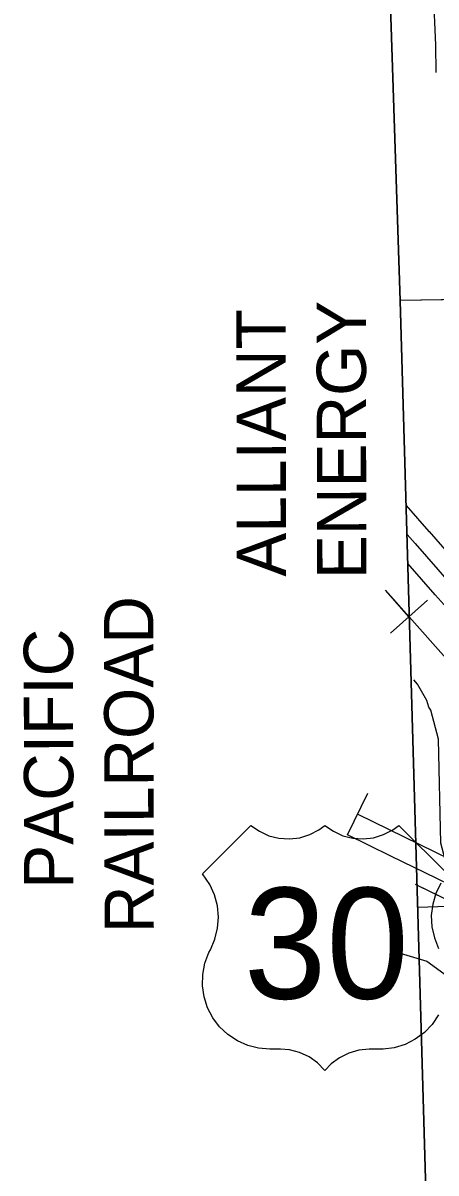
# Model space of a CAD drawing. Extents: x 128.7 to 185.5, y -21.4 to 12.6.
# Drawn here: x 133.449 to 134.119, y -9.118 to -7.251 of the extents above; entities that cross this region are included whole.
import ezdxf

# ---------------------------------------------------------------- set-up
doc = ezdxf.new("R2010")
doc.units = 0
for name, color, linetype in [('tdCoClipBndry', 7, 'Continuous'), ('tdCoCoBndry', 7, 'Continuous'), ('tdCoHydroRiver', 7, 'Continuous'), ('tdCoPipe', 7, 'Continuous'), ('tdCoPipeTxt', 7, 'Continuous'), ('tdCoPriCL', 7, 'Continuous'), ('tdCoPrimary', 7, 'Continuous'), ('tdCoPriNonDiv', 7, 'Continuous'), ('tdCoPriNonDivCL', 7, 'Continuous'), ('tdCoRRCL', 7, 'Continuous'), ('tdCoRROwnerTxt', 7, 'Continuous'), ('tdCoSecRteBand', 7, 'Continuous'), ('tdCoSecRteCL', 7, 'Continuous'), ('tdCoSectLine', 7, 'Continuous'), ('tdCoSectLinePart', 7, 'Continuous'), ('tdCoShieldUsRte', 7, 'Continuous'), ('tdCoSurfAsphalt', 7, 'Continuous')]:
    doc.layers.add(name, color=color, linetype=linetype)

msp = doc.modelspace()

# ---------------------------------------------------------------- linework, layer by layer
at = {"layer": 'tdCoClipBndry'}
msp.add_lwpolyline([(140.0473, -13.6827), (139.3409, -13.68), (138.3408, -13.7014), (135.3417, -13.7884), (134.3324, -13.8229), (134.2979, -13.818), (134.2605, -13.7958), (134.2397, -13.7678), (134.2291, -13.7257), (134.1751, -11.7221), (134.1418, -10.7117), (134.1187, -9.7087), (134.0612, -7.7025), (133.8962, -2.6807)], dxfattribs=at)
at = {"layer": 'tdCoCoBndry'}
msp.add_lwpolyline([(133.8962, -2.6807), (134.0612, -7.7025), (134.1187, -9.7087), (134.1418, -10.7117), (134.1751, -11.7221), (134.2291, -13.7257), (134.2397, -13.7678), (134.2605, -13.7958), (134.2979, -13.818), (134.3318, -13.8228), (134.3294, -13.723), (134.3001, -12.7212), (134.2754, -11.7191), (134.2421, -10.7094), (134.219, -9.7062), (134.1879, -8.683), (134.1615, -7.6994), (134.1297, -6.7029)], dxfattribs=at)
at = {"layer": 'tdCoHydroRiver'}
for points in [[(134.1586, -8.8038), (134.1525, -8.6509), (134.1454, -8.6259), (134.1339, -8.6088), (134.1268, -8.5822), (134.1234, -8.4135), (134.1109, -8.3665), (134.1076, -8.3619), (134.1041, -8.3509), (134.0892, -8.3245), (134.0831, -8.3171)], [(134.0553, -8.7596), (134.1041, -8.7738), (134.1379, -8.7981), (134.1586, -8.8038), (134.1604, -8.8116), (134.2009, -8.8451), (134.2621, -8.8891), (134.3164, -8.9096), (134.4386, -8.9312), (134.4721, -8.9444), (134.5193, -8.9919), (134.5452, -9.0148), (134.5835, -9.0294), (134.9473, -9.0565), (135.0122, -9.0656), (135.0921, -9.098), (135.126, -9.1238)]]:
    msp.add_lwpolyline(points, dxfattribs=at)
at = {"layer": 'tdCoPipe'}
msp.add_line((134.045, -8.2417), (134.1053, -8.1882), dxfattribs=at)
for points in [[(136.9009, -9.4255), (136.8169, -9.4094), (136.5505, -9.3406), (136.5159, -9.3231), (136.4089, -9.2225), (136.4044, -9.218), (135.9635, -8.7378), (135.3912, -8.758), (135.204, -8.7612), (134.6962, -8.7684), (134.6297, -8.7639), (134.5618, -8.7314), (134.4564, -8.6441), (134.037, -8.172)], [(134.0751, -8.215), (134.037, -8.172)]]:
    msp.add_lwpolyline(points, dxfattribs=at)
at = {"layer": 'tdCoPriCL'}
msp.add_lwpolyline([(134.0884, -8.6507), (134.1751, -8.6926)], dxfattribs=at)
at = {"layer": 'tdCoPrimary'}
for points in [[(134.0884, -8.6505), (134.1754, -8.6926), (134.1883, -8.6989)], [(134.0884, -8.6505), (134.1754, -8.6926), (134.1883, -8.6989)], [(134.0884, -8.6505), (134.1754, -8.6926)]]:
    msp.add_lwpolyline(points, dxfattribs=at)
at = {"layer": 'tdCoPriNonDiv'}
msp.add_lwpolyline([(134.0851, -8.6491), (134.3608, -8.7836), (134.4273, -8.8152), (134.4917, -8.8423), (134.5629, -8.8687), (134.6384, -8.8922), (135.3035, -9.0723), (136.2808, -9.3366)], dxfattribs=at)
at = {"layer": 'tdCoPriNonDivCL'}
for points in [[(134.0884, -8.6507), (134.1751, -8.6926)], [(134.0884, -8.6507), (134.1751, -8.6926), (134.1879, -8.6989)]]:
    msp.add_lwpolyline(points, dxfattribs=at)
at = {"layer": 'tdCoRRCL'}
msp.add_line((133.9757, -8.5688), (134.0086, -8.5014), dxfattribs=at)
for points in [[(133.992, -8.5352), (134.2166, -8.645), (134.4406, -8.754), (134.4603, -8.7626), (134.4791, -8.7707), (134.4969, -8.7778), (134.5147, -8.7849), (134.5414, -8.7951), (134.5789, -8.8085), (134.6146, -8.82), (134.6502, -8.8316), (134.6697, -8.8374), (134.911, -8.9025), (135.152, -8.9678), (135.3934, -9.0327), (135.6349, -9.098)], [(135.481, -9.095), (135.3832, -9.0688), (135.2626, -9.0366), (135.1848, -9.0154), (135.0629, -8.9826), (134.9732, -8.9582), (134.8705, -8.9307), (134.774, -8.9047), (134.7045, -8.8861), (134.6398, -8.868), (134.5685, -8.845), (134.531, -8.8316), (134.5042, -8.8214), (134.4686, -8.8072), (134.4311, -8.791), (134.3826, -8.7687), (134.3257, -8.7406), (134.2712, -8.7136), (134.1872, -8.6725), (134.1205, -8.64), (134.0458, -8.6033), (133.9755, -8.5689)]]:
    msp.add_lwpolyline(points, dxfattribs=at)
at = {"layer": 'tdCoSecRteBand'}
for points in [[(134.1193, -7.3318), (134.1186, -7.2875), (134.1152, -7.2001)], [(134.0707, -8.0346), (134.1077, -8.0764), (134.1078, -8.0765), (134.1078, -8.0766), (134.1443, -8.1185)], [(134.1371, -8.2012), (134.1178, -8.1794), (134.1177, -8.1793), (134.1176, -8.1792), (134.0734, -8.1285)]]:
    msp.add_lwpolyline(points, dxfattribs=at)
at = {"layer": 'tdCoSecRteCL'}
msp.add_lwpolyline([(134.0721, -8.0815), (134.0852, -8.0963), (134.1402, -8.1594), (134.1617, -8.1836), (134.1689, -8.1919), (134.1749, -8.1988), (134.1889, -8.2147), (134.241, -8.2733), (134.2735, -8.3113), (134.3746, -8.4265), (134.4513, -8.5148), (134.5103, -8.5816), (134.5372, -8.6124), (134.5561, -8.6341), (134.5687, -8.6437), (134.5801, -8.6531), (134.5921, -8.6593), (134.6136, -8.6701), (134.6286, -8.6763), (134.6457, -8.6802), (134.6703, -8.6835), (134.6968, -8.6838)], dxfattribs=at)
at = {"layer": 'tdCoSectLine'}
for points in [[(134.0612, -7.7013), (134.1612, -7.6994)], [(134.0894, -8.6862), (134.1875, -8.683)]]:
    msp.add_lwpolyline(points, dxfattribs=at)
at = {"layer": 'tdCoSectLinePart'}
for points in [[(134.0612, -7.7013), (134.1307, -7.7)], [(134.0894, -8.6862), (134.1875, -8.683)]]:
    msp.add_lwpolyline(points, dxfattribs=at)
at = {"layer": 'tdCoShieldUsRte'}
for points in [[(134.1233, -8.8613), (134.1129, -8.8765), (134.1002, -8.8897), (134.0854, -8.9007), (134.069, -8.909), (134.0514, -8.9144), (134.0331, -8.9169), (134.024, -8.917), (134.0107, -8.917), (133.9938, -8.9185), (133.9776, -8.9231), (133.9624, -8.9306), (133.9488, -8.9406), (133.9387, -8.9513), (133.9269, -8.9392), (133.9131, -8.9294), (133.8978, -8.9223), (133.8814, -8.9181), (133.8668, -8.917), (133.8497, -8.917), (133.8313, -8.9154), (133.8135, -8.9109), (133.7967, -8.9034), (133.7814, -8.8932), (133.768, -8.8805), (133.7569, -8.8659), (133.7484, -8.8495), (133.7428, -8.832), (133.7401, -8.8138), (133.7406, -8.7954), (133.7441, -8.7774), (133.7506, -8.7601), (133.753, -8.7554), (133.7603, -8.7385), (133.7647, -8.7206), (133.766, -8.7023), (133.7643, -8.684), (133.7595, -8.6662), (133.7518, -8.6495), (133.7399, -8.6324), (133.8187, -8.5535), (133.8325, -8.5632), (133.8479, -8.5703), (133.8643, -8.5745), (133.8811, -8.5756), (133.8979, -8.5736), (133.9141, -8.5686), (133.929, -8.5607), (133.9387, -8.5535), (133.9525, -8.5632), (133.9679, -8.5703), (133.9843, -8.5745), (134.0011, -8.5756), (134.0179, -8.5736), (134.0341, -8.5686), (134.049, -8.5607), (134.0587, -8.5535), (134.1376, -8.6324)], [(134.1269, -8.6473), (134.1189, -8.6639), (134.1137, -8.6815), (134.1115, -8.6998), (134.1124, -8.7182), (134.1164, -8.7362), (134.1234, -8.7532)]]:
    msp.add_lwpolyline(points, dxfattribs=at)
at = {"layer": 'tdCoSurfAsphalt'}
msp.add_lwpolyline([(134.0721, -8.0815), (134.0852, -8.0963), (134.1402, -8.1594)], dxfattribs=at)

# ---------------------------------------------------------------- texts
at = {"layer": 'tdCoPipeTxt'}
for s, p in [('ENERGY', (134.0061, -8.1537)), ('ALLIANT', (133.8758, -8.1499))]:
    msp.add_text(s, height=0.08, rotation=90.1002, dxfattribs=at).set_placement(p)
at = {"layer": 'tdCoRROwnerTxt'}
for s, p in [('RAILROAD', (133.6612, -8.7284)), ('PACIFIC ', (133.5307, -8.6564))]:
    msp.add_text(s, height=0.08, rotation=90.0995, dxfattribs=at).set_placement(p)
at = {"layer": 'tdCoShieldUsRte'}
msp.add_text('30', height=0.18, dxfattribs=at).set_placement((133.8073, -8.8348))

doc.saveas('drawing.dxf')
